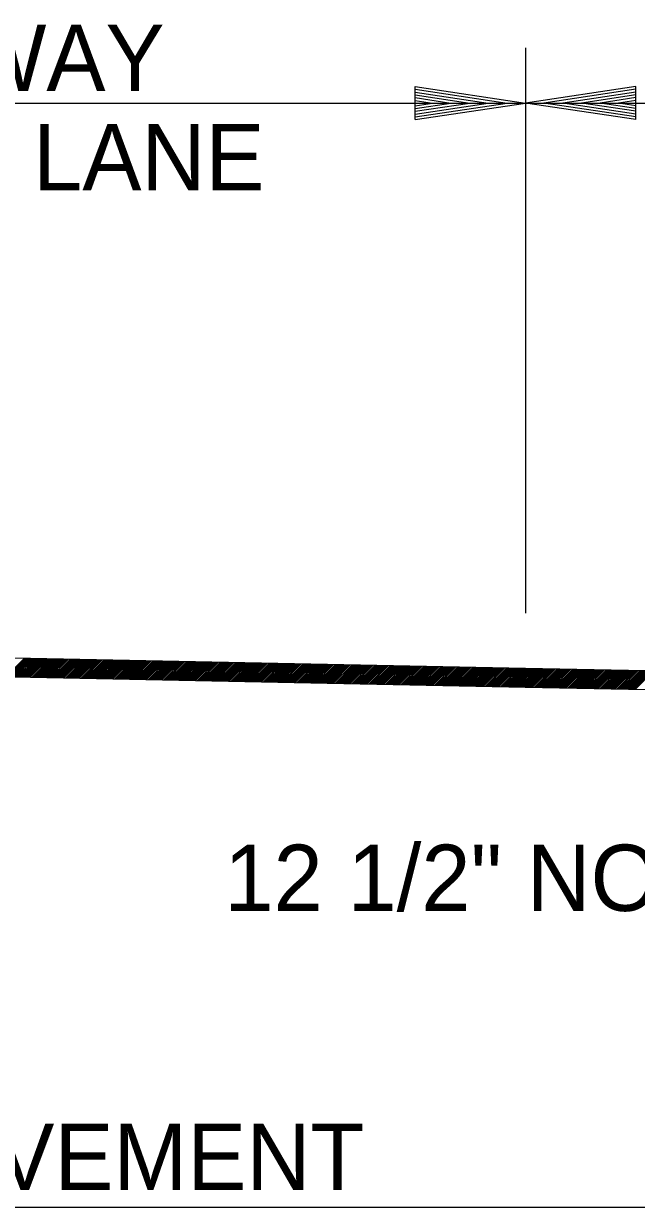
# Model space of a CAD drawing. Extents: x 2263886 to 2266026, y -3122850 to -3121850.
# Drawn here: x 2265601.06 to 2265606.6, y -3122413.5 to -3122402.78 of the extents above; entities that cross this region are included whole.
import ezdxf

# ---------------------------------------------------------------- set-up
doc = ezdxf.new("R2010")
doc.units = 0
doc.layers.add('R_Border Prem', color=7, linetype='Continuous')

msp = doc.modelspace()

# ---------------------------------------------------------------- linework, layer by layer
at = {"layer": 'R_Border Prem'}
for p, q in [((2265605.599, -3122403.003), (2265605.599, -3122407.503)), ((2265604.599, -3122403.353), (2265605.599, -3122403.503)), ((2265604.599, -3122403.653), (2265604.599, -3122403.353)), ((2265604.599, -3122403.378), (2265605.432, -3122403.503)), ((2265604.599, -3122403.404), (2265605.26, -3122403.503)), ((2265604.599, -3122403.429), (2265605.094, -3122403.503)), ((2265606.599, -3122403.353), (2265605.599, -3122403.503)), ((2265606.599, -3122403.378), (2265605.766, -3122403.503)), ((2265606.599, -3122403.404), (2265605.938, -3122403.503)), ((2265606.599, -3122403.429), (2265606.105, -3122403.503)), ((2265606.599, -3122403.653), (2265606.599, -3122403.353)), ((2265593.599, -3122403.503), (2265605.599, -3122403.503)), ((2265604.599, -3122403.454), (2265604.924, -3122403.503)), ((2265604.599, -3122403.48), (2265604.757, -3122403.503)), ((2265604.599, -3122403.653), (2265605.599, -3122403.503)), ((2265604.599, -3122403.552), (2265604.924, -3122403.503)), ((2265604.599, -3122403.603), (2265605.26, -3122403.503)), ((2265604.599, -3122403.628), (2265605.432, -3122403.503)), ((2265604.599, -3122403.578), (2265605.094, -3122403.503)), ((2265604.599, -3122403.527), (2265604.757, -3122403.503)), ((2265605.599, -3122403.503), (2265617.599, -3122403.503)), ((2265606.599, -3122403.653), (2265605.599, -3122403.503)), ((2265606.599, -3122403.628), (2265605.766, -3122403.503)), ((2265606.599, -3122403.603), (2265605.938, -3122403.503)), ((2265606.599, -3122403.578), (2265606.105, -3122403.503)), ((2265606.599, -3122403.454), (2265606.274, -3122403.503)), ((2265606.599, -3122403.552), (2265606.274, -3122403.503)), ((2265606.599, -3122403.48), (2265606.441, -3122403.503)), ((2265606.599, -3122403.527), (2265606.441, -3122403.503)), ((2265605.599, -3122407.503), (2265605.599, -3122408.123)), ((2265605.599, -3122408.623), (2265599.599, -3122408.503)), ((2265600.893, -3122408.699), (2265601.059, -3122408.532)), ((2265600.906, -3122408.699), (2265601.073, -3122408.533)), ((2265600.92, -3122408.7), (2265601.087, -3122408.533)), ((2265600.934, -3122408.7), (2265601.101, -3122408.533)), ((2265600.948, -3122408.7), (2265601.115, -3122408.533)), ((2265600.962, -3122408.7), (2265601.129, -3122408.534)), ((2265600.976, -3122408.701), (2265601.142, -3122408.534)), ((2265600.99, -3122408.701), (2265601.156, -3122408.534)), ((2265601.004, -3122408.701), (2265601.17, -3122408.534)), ((2265601.017, -3122408.701), (2265601.184, -3122408.535)), ((2265601.031, -3122408.702), (2265601.198, -3122408.535)), ((2265601.045, -3122408.702), (2265601.212, -3122408.535)), ((2265601.059, -3122408.702), (2265601.226, -3122408.536)), ((2265601.073, -3122408.703), (2265601.24, -3122408.536)), ((2265601.087, -3122408.703), (2265601.253, -3122408.536)), ((2265601.101, -3122408.703), (2265601.267, -3122408.536)), ((2265601.114, -3122408.703), (2265601.281, -3122408.537)), ((2265601.128, -3122408.704), (2265601.295, -3122408.537)), ((2265601.142, -3122408.704), (2265601.309, -3122408.537)), ((2265601.156, -3122408.704), (2265601.323, -3122408.538)), ((2265601.17, -3122408.705), (2265601.337, -3122408.538)), ((2265601.184, -3122408.705), (2265601.35, -3122408.538)), ((2265601.198, -3122408.705), (2265601.364, -3122408.538)), ((2265601.211, -3122408.705), (2265601.378, -3122408.539)), ((2265601.225, -3122408.706), (2265601.392, -3122408.539)), ((2265601.239, -3122408.706), (2265601.406, -3122408.539)), ((2265601.253, -3122408.706), (2265601.42, -3122408.539)), ((2265601.267, -3122408.706), (2265601.434, -3122408.54)), ((2265601.281, -3122408.707), (2265601.447, -3122408.54)), ((2265601.295, -3122408.707), (2265601.461, -3122408.54)), ((2265601.309, -3122408.707), (2265601.475, -3122408.541)), ((2265601.322, -3122408.708), (2265601.489, -3122408.541)), ((2265601.336, -3122408.708), (2265601.503, -3122408.541)), ((2265601.35, -3122408.708), (2265601.517, -3122408.541)), ((2265601.364, -3122408.708), (2265601.531, -3122408.542)), ((2265601.378, -3122408.709), (2265601.545, -3122408.542)), ((2265601.392, -3122408.709), (2265601.558, -3122408.542)), ((2265601.406, -3122408.709), (2265601.572, -3122408.543)), ((2265601.419, -3122408.709), (2265601.586, -3122408.543)), ((2265601.433, -3122408.71), (2265601.6, -3122408.543)), ((2265601.447, -3122408.71), (2265601.614, -3122408.543)), ((2265601.461, -3122408.71), (2265601.628, -3122408.544)), ((2265601.475, -3122408.711), (2265601.642, -3122408.544)), ((2265601.489, -3122408.711), (2265601.655, -3122408.544)), ((2265601.503, -3122408.711), (2265601.669, -3122408.544)), ((2265601.516, -3122408.711), (2265601.683, -3122408.545)), ((2265601.53, -3122408.712), (2265601.697, -3122408.545)), ((2265601.544, -3122408.712), (2265601.711, -3122408.545)), ((2265601.558, -3122408.712), (2265601.725, -3122408.546)), ((2265601.572, -3122408.713), (2265601.739, -3122408.546)), ((2265601.586, -3122408.713), (2265601.753, -3122408.546)), ((2265601.6, -3122408.713), (2265601.766, -3122408.546)), ((2265601.614, -3122408.713), (2265601.78, -3122408.547)), ((2265601.627, -3122408.714), (2265601.794, -3122408.547)), ((2265601.641, -3122408.714), (2265601.808, -3122408.547)), ((2265601.655, -3122408.714), (2265601.822, -3122408.548)), ((2265601.669, -3122408.714), (2265601.836, -3122408.548)), ((2265601.683, -3122408.715), (2265601.85, -3122408.548)), ((2265601.697, -3122408.715), (2265601.863, -3122408.548)), ((2265601.711, -3122408.715), (2265601.877, -3122408.549)), ((2265601.724, -3122408.716), (2265601.891, -3122408.549)), ((2265601.738, -3122408.716), (2265601.905, -3122408.549)), ((2265601.752, -3122408.716), (2265601.919, -3122408.549)), ((2265601.766, -3122408.716), (2265601.933, -3122408.55)), ((2265601.78, -3122408.717), (2265601.947, -3122408.55)), ((2265601.794, -3122408.717), (2265601.96, -3122408.55)), ((2265601.808, -3122408.717), (2265601.974, -3122408.551)), ((2265601.822, -3122408.718), (2265601.988, -3122408.551)), ((2265601.835, -3122408.718), (2265602.002, -3122408.551)), ((2265601.849, -3122408.718), (2265602.016, -3122408.551)), ((2265601.863, -3122408.718), (2265602.03, -3122408.552)), ((2265601.877, -3122408.719), (2265602.044, -3122408.552)), ((2265601.891, -3122408.719), (2265602.058, -3122408.552)), ((2265601.905, -3122408.719), (2265602.071, -3122408.553)), ((2265601.919, -3122408.719), (2265602.085, -3122408.553)), ((2265601.932, -3122408.72), (2265602.099, -3122408.553)), ((2265601.946, -3122408.72), (2265602.113, -3122408.553)), ((2265601.96, -3122408.72), (2265602.127, -3122408.554)), ((2265601.974, -3122408.721), (2265602.141, -3122408.554)), ((2265601.988, -3122408.721), (2265602.155, -3122408.554)), ((2265602.002, -3122408.721), (2265602.168, -3122408.554)), ((2265602.016, -3122408.721), (2265602.182, -3122408.555)), ((2265602.029, -3122408.722), (2265602.196, -3122408.555)), ((2265602.043, -3122408.722), (2265602.21, -3122408.555)), ((2265602.057, -3122408.722), (2265602.224, -3122408.556)), ((2265602.071, -3122408.723), (2265602.238, -3122408.556)), ((2265602.085, -3122408.723), (2265602.252, -3122408.556)), ((2265602.099, -3122408.723), (2265602.266, -3122408.556)), ((2265602.113, -3122408.723), (2265602.279, -3122408.557)), ((2265602.127, -3122408.724), (2265602.293, -3122408.557)), ((2265602.14, -3122408.724), (2265602.307, -3122408.557)), ((2265602.154, -3122408.724), (2265602.321, -3122408.557)), ((2265602.168, -3122408.724), (2265602.335, -3122408.558)), ((2265602.182, -3122408.725), (2265602.349, -3122408.558)), ((2265602.196, -3122408.725), (2265602.363, -3122408.558)), ((2265602.21, -3122408.725), (2265602.376, -3122408.559)), ((2265602.224, -3122408.726), (2265602.39, -3122408.559)), ((2265602.237, -3122408.726), (2265602.404, -3122408.559)), ((2265602.251, -3122408.726), (2265602.418, -3122408.559)), ((2265602.265, -3122408.726), (2265602.432, -3122408.56)), ((2265602.279, -3122408.727), (2265602.446, -3122408.56)), ((2265602.293, -3122408.727), (2265602.46, -3122408.56)), ((2265602.307, -3122408.727), (2265602.473, -3122408.561)), ((2265602.321, -3122408.728), (2265602.487, -3122408.561)), ((2265602.335, -3122408.728), (2265602.501, -3122408.561)), ((2265602.348, -3122408.728), (2265602.515, -3122408.561)), ((2265602.362, -3122408.728), (2265602.529, -3122408.562)), ((2265602.376, -3122408.729), (2265602.543, -3122408.562)), ((2265602.39, -3122408.729), (2265602.557, -3122408.562)), ((2265602.404, -3122408.729), (2265602.571, -3122408.562)), ((2265602.418, -3122408.729), (2265602.584, -3122408.563)), ((2265602.432, -3122408.73), (2265602.598, -3122408.563)), ((2265602.445, -3122408.73), (2265602.612, -3122408.563)), ((2265602.459, -3122408.73), (2265602.626, -3122408.564)), ((2265602.473, -3122408.731), (2265602.64, -3122408.564)), ((2265602.487, -3122408.731), (2265602.654, -3122408.564)), ((2265602.501, -3122408.731), (2265602.668, -3122408.564)), ((2265602.515, -3122408.731), (2265602.681, -3122408.565)), ((2265602.529, -3122408.732), (2265602.695, -3122408.565)), ((2265602.542, -3122408.732), (2265602.709, -3122408.565)), ((2265602.556, -3122408.732), (2265602.723, -3122408.566)), ((2265602.57, -3122408.733), (2265602.737, -3122408.566)), ((2265602.584, -3122408.733), (2265602.751, -3122408.566)), ((2265602.598, -3122408.733), (2265602.765, -3122408.566)), ((2265602.612, -3122408.733), (2265602.779, -3122408.567)), ((2265602.626, -3122408.734), (2265602.792, -3122408.567)), ((2265602.64, -3122408.734), (2265602.806, -3122408.567)), ((2265602.653, -3122408.734), (2265602.82, -3122408.567)), ((2265602.667, -3122408.734), (2265602.834, -3122408.568)), ((2265602.681, -3122408.735), (2265602.848, -3122408.568)), ((2265602.695, -3122408.735), (2265602.862, -3122408.568)), ((2265602.709, -3122408.735), (2265602.876, -3122408.569)), ((2265602.723, -3122408.736), (2265602.889, -3122408.569)), ((2265602.737, -3122408.736), (2265602.903, -3122408.569)), ((2265602.75, -3122408.736), (2265602.917, -3122408.569)), ((2265602.764, -3122408.736), (2265602.931, -3122408.57)), ((2265602.778, -3122408.737), (2265602.945, -3122408.57)), ((2265602.792, -3122408.737), (2265602.959, -3122408.57)), ((2265602.806, -3122408.737), (2265602.973, -3122408.571)), ((2265602.82, -3122408.738), (2265602.986, -3122408.571)), ((2265602.834, -3122408.738), (2265603, -3122408.571)), ((2265602.848, -3122408.738), (2265603.014, -3122408.571)), ((2265602.861, -3122408.738), (2265603.028, -3122408.572)), ((2265602.875, -3122408.739), (2265603.042, -3122408.572)), ((2265602.889, -3122408.739), (2265603.056, -3122408.572)), ((2265602.903, -3122408.739), (2265603.07, -3122408.572)), ((2265602.917, -3122408.739), (2265603.084, -3122408.573)), ((2265602.931, -3122408.74), (2265603.097, -3122408.573)), ((2265602.945, -3122408.74), (2265603.111, -3122408.573)), ((2265602.958, -3122408.74), (2265603.125, -3122408.574)), ((2265602.972, -3122408.741), (2265603.139, -3122408.574)), ((2265602.986, -3122408.741), (2265603.153, -3122408.574)), ((2265603, -3122408.741), (2265603.167, -3122408.574)), ((2265603.014, -3122408.741), (2265603.181, -3122408.575)), ((2265603.028, -3122408.742), (2265603.194, -3122408.575)), ((2265603.042, -3122408.742), (2265603.208, -3122408.575)), ((2265603.055, -3122408.742), (2265603.222, -3122408.576)), ((2265603.069, -3122408.742), (2265603.236, -3122408.576)), ((2265603.083, -3122408.743), (2265603.25, -3122408.576)), ((2265603.097, -3122408.743), (2265603.264, -3122408.576)), ((2265603.111, -3122408.743), (2265603.278, -3122408.577)), ((2265603.125, -3122408.744), (2265603.292, -3122408.577)), ((2265603.139, -3122408.744), (2265603.305, -3122408.577)), ((2265603.153, -3122408.744), (2265603.319, -3122408.577)), ((2265603.166, -3122408.744), (2265603.333, -3122408.578)), ((2265603.18, -3122408.745), (2265603.347, -3122408.578)), ((2265603.194, -3122408.745), (2265603.361, -3122408.578)), ((2265603.208, -3122408.745), (2265603.375, -3122408.579)), ((2265603.222, -3122408.746), (2265603.389, -3122408.579)), ((2265603.236, -3122408.746), (2265603.402, -3122408.579)), ((2265603.25, -3122408.746), (2265603.416, -3122408.579)), ((2265603.263, -3122408.746), (2265603.43, -3122408.58)), ((2265603.277, -3122408.747), (2265603.444, -3122408.58)), ((2265603.291, -3122408.747), (2265603.458, -3122408.58)), ((2265603.305, -3122408.747), (2265603.472, -3122408.581)), ((2265603.319, -3122408.747), (2265603.486, -3122408.581)), ((2265603.333, -3122408.748), (2265603.499, -3122408.581)), ((2265603.347, -3122408.748), (2265603.513, -3122408.581)), ((2265603.361, -3122408.748), (2265603.527, -3122408.582)), ((2265603.374, -3122408.749), (2265603.541, -3122408.582)), ((2265603.388, -3122408.749), (2265603.555, -3122408.582)), ((2265603.402, -3122408.749), (2265603.569, -3122408.582)), ((2265603.416, -3122408.749), (2265603.583, -3122408.583)), ((2265603.43, -3122408.75), (2265603.597, -3122408.583)), ((2265599.599, -3122408.673), (2265605.596, -3122408.793)), ((2265603.444, -3122408.75), (2265603.61, -3122408.583)), ((2265603.458, -3122408.75), (2265603.624, -3122408.584)), ((2265603.471, -3122408.751), (2265603.638, -3122408.584)), ((2265603.485, -3122408.751), (2265603.652, -3122408.584)), ((2265603.499, -3122408.751), (2265603.666, -3122408.584)), ((2265603.513, -3122408.751), (2265603.68, -3122408.585)), ((2265603.527, -3122408.752), (2265603.694, -3122408.585)), ((2265603.541, -3122408.752), (2265603.707, -3122408.585)), ((2265603.555, -3122408.752), (2265603.721, -3122408.585)), ((2265603.568, -3122408.752), (2265603.735, -3122408.586)), ((2265603.582, -3122408.753), (2265603.749, -3122408.586)), ((2265603.596, -3122408.753), (2265603.763, -3122408.586)), ((2265603.61, -3122408.753), (2265603.777, -3122408.587)), ((2265603.624, -3122408.754), (2265603.791, -3122408.587)), ((2265603.638, -3122408.754), (2265603.805, -3122408.587)), ((2265603.652, -3122408.754), (2265603.818, -3122408.587)), ((2265603.666, -3122408.754), (2265603.832, -3122408.588)), ((2265603.679, -3122408.755), (2265603.846, -3122408.588)), ((2265603.693, -3122408.755), (2265603.86, -3122408.588)), ((2265603.707, -3122408.755), (2265603.874, -3122408.589)), ((2265603.721, -3122408.756), (2265603.888, -3122408.589)), ((2265603.735, -3122408.756), (2265603.902, -3122408.589)), ((2265603.749, -3122408.756), (2265603.915, -3122408.589)), ((2265603.763, -3122408.756), (2265603.929, -3122408.59)), ((2265603.776, -3122408.757), (2265603.943, -3122408.59)), ((2265603.79, -3122408.757), (2265603.957, -3122408.59)), ((2265603.804, -3122408.757), (2265603.971, -3122408.59)), ((2265603.818, -3122408.757), (2265603.985, -3122408.591)), ((2265603.832, -3122408.758), (2265603.999, -3122408.591)), ((2265603.846, -3122408.758), (2265604.012, -3122408.591)), ((2265603.86, -3122408.758), (2265604.026, -3122408.592)), ((2265603.874, -3122408.759), (2265604.04, -3122408.592)), ((2265603.887, -3122408.759), (2265604.054, -3122408.592)), ((2265603.901, -3122408.759), (2265604.068, -3122408.592)), ((2265603.915, -3122408.759), (2265604.082, -3122408.593)), ((2265603.929, -3122408.76), (2265604.096, -3122408.593)), ((2265603.943, -3122408.76), (2265604.11, -3122408.593)), ((2265603.957, -3122408.76), (2265604.123, -3122408.594)), ((2265603.971, -3122408.761), (2265604.137, -3122408.594)), ((2265603.984, -3122408.761), (2265604.151, -3122408.594)), ((2265603.998, -3122408.761), (2265604.165, -3122408.594)), ((2265604.012, -3122408.761), (2265604.179, -3122408.595)), ((2265604.026, -3122408.762), (2265604.193, -3122408.595)), ((2265604.04, -3122408.762), (2265604.207, -3122408.595)), ((2265604.054, -3122408.762), (2265604.22, -3122408.595)), ((2265604.068, -3122408.762), (2265604.234, -3122408.596)), ((2265604.081, -3122408.763), (2265604.248, -3122408.596)), ((2265604.095, -3122408.763), (2265604.262, -3122408.596)), ((2265604.109, -3122408.763), (2265604.276, -3122408.597)), ((2265604.123, -3122408.764), (2265604.29, -3122408.597)), ((2265604.137, -3122408.764), (2265604.304, -3122408.597)), ((2265604.151, -3122408.764), (2265604.318, -3122408.597)), ((2265604.165, -3122408.764), (2265604.331, -3122408.598)), ((2265604.179, -3122408.765), (2265604.345, -3122408.598)), ((2265604.192, -3122408.765), (2265604.359, -3122408.598)), ((2265604.206, -3122408.765), (2265604.373, -3122408.599)), ((2265604.22, -3122408.766), (2265604.387, -3122408.599)), ((2265604.234, -3122408.766), (2265604.401, -3122408.599)), ((2265604.248, -3122408.766), (2265604.415, -3122408.599)), ((2265604.262, -3122408.766), (2265604.428, -3122408.6)), ((2265604.276, -3122408.767), (2265604.442, -3122408.6)), ((2265604.289, -3122408.767), (2265604.456, -3122408.6)), ((2265604.303, -3122408.767), (2265604.47, -3122408.6)), ((2265604.317, -3122408.767), (2265604.484, -3122408.601)), ((2265604.331, -3122408.768), (2265604.498, -3122408.601)), ((2265604.345, -3122408.768), (2265604.512, -3122408.601)), ((2265604.359, -3122408.768), (2265604.525, -3122408.602)), ((2265604.373, -3122408.769), (2265604.539, -3122408.602)), ((2265604.387, -3122408.769), (2265604.553, -3122408.602)), ((2265604.4, -3122408.769), (2265604.567, -3122408.602)), ((2265604.414, -3122408.769), (2265604.581, -3122408.603)), ((2265604.428, -3122408.77), (2265604.595, -3122408.603)), ((2265604.442, -3122408.77), (2265604.609, -3122408.603)), ((2265604.456, -3122408.77), (2265604.623, -3122408.604)), ((2265604.47, -3122408.771), (2265604.636, -3122408.604)), ((2265604.484, -3122408.771), (2265604.65, -3122408.604)), ((2265604.497, -3122408.771), (2265604.664, -3122408.604)), ((2265604.511, -3122408.771), (2265604.678, -3122408.605)), ((2265604.525, -3122408.772), (2265604.692, -3122408.605)), ((2265604.539, -3122408.772), (2265604.706, -3122408.605)), ((2265604.553, -3122408.772), (2265604.72, -3122408.605)), ((2265604.567, -3122408.772), (2265604.733, -3122408.606)), ((2265604.581, -3122408.773), (2265604.747, -3122408.606)), ((2265604.594, -3122408.773), (2265604.761, -3122408.606)), ((2265604.608, -3122408.773), (2265604.775, -3122408.607)), ((2265604.622, -3122408.774), (2265604.789, -3122408.607)), ((2265604.636, -3122408.774), (2265604.803, -3122408.607)), ((2265604.65, -3122408.774), (2265604.817, -3122408.607)), ((2265604.664, -3122408.774), (2265604.831, -3122408.608)), ((2265604.678, -3122408.775), (2265604.844, -3122408.608)), ((2265604.692, -3122408.775), (2265604.858, -3122408.608)), ((2265604.705, -3122408.775), (2265604.872, -3122408.609)), ((2265604.719, -3122408.775), (2265604.886, -3122408.609)), ((2265604.733, -3122408.776), (2265604.9, -3122408.609)), ((2265604.747, -3122408.776), (2265604.914, -3122408.609)), ((2265604.761, -3122408.776), (2265604.928, -3122408.61)), ((2265604.775, -3122408.777), (2265604.941, -3122408.61)), ((2265604.789, -3122408.777), (2265604.955, -3122408.61)), ((2265604.802, -3122408.777), (2265604.969, -3122408.61)), ((2265604.816, -3122408.777), (2265604.983, -3122408.611)), ((2265604.83, -3122408.778), (2265604.997, -3122408.611)), ((2265604.844, -3122408.778), (2265605.011, -3122408.611)), ((2265604.858, -3122408.778), (2265605.025, -3122408.612)), ((2265604.872, -3122408.779), (2265605.038, -3122408.612)), ((2265604.886, -3122408.779), (2265605.052, -3122408.612)), ((2265604.9, -3122408.779), (2265605.066, -3122408.612)), ((2265604.913, -3122408.779), (2265605.08, -3122408.613)), ((2265604.927, -3122408.78), (2265605.094, -3122408.613)), ((2265604.941, -3122408.78), (2265605.108, -3122408.613)), ((2265604.955, -3122408.78), (2265605.122, -3122408.614)), ((2265604.969, -3122408.78), (2265605.136, -3122408.614)), ((2265604.983, -3122408.781), (2265605.149, -3122408.614)), ((2265604.997, -3122408.781), (2265605.163, -3122408.614)), ((2265605.01, -3122408.781), (2265605.177, -3122408.615)), ((2265605.024, -3122408.782), (2265605.191, -3122408.615)), ((2265605.038, -3122408.782), (2265605.205, -3122408.615)), ((2265605.052, -3122408.782), (2265605.219, -3122408.615)), ((2265605.066, -3122408.782), (2265605.233, -3122408.616)), ((2265605.08, -3122408.783), (2265605.246, -3122408.616)), ((2265605.094, -3122408.783), (2265605.26, -3122408.616)), ((2265605.107, -3122408.783), (2265605.274, -3122408.617)), ((2265605.121, -3122408.784), (2265605.288, -3122408.617)), ((2265605.135, -3122408.784), (2265605.302, -3122408.617)), ((2265605.149, -3122408.784), (2265605.316, -3122408.617)), ((2265605.163, -3122408.784), (2265605.33, -3122408.618)), ((2265605.177, -3122408.785), (2265605.344, -3122408.618)), ((2265605.191, -3122408.785), (2265605.357, -3122408.618)), ((2265605.205, -3122408.785), (2265605.371, -3122408.618)), ((2265605.218, -3122408.785), (2265605.385, -3122408.619)), ((2265605.232, -3122408.786), (2265605.399, -3122408.619)), ((2265605.246, -3122408.786), (2265605.413, -3122408.619)), ((2265605.26, -3122408.786), (2265605.427, -3122408.62)), ((2265605.274, -3122408.787), (2265605.441, -3122408.62)), ((2265605.288, -3122408.787), (2265605.454, -3122408.62)), ((2265605.302, -3122408.787), (2265605.468, -3122408.62)), ((2265605.315, -3122408.787), (2265605.482, -3122408.621)), ((2265605.329, -3122408.788), (2265605.496, -3122408.621)), ((2265605.343, -3122408.788), (2265605.51, -3122408.621)), ((2265605.357, -3122408.788), (2265605.524, -3122408.622)), ((2265605.371, -3122408.789), (2265605.538, -3122408.622)), ((2265605.385, -3122408.789), (2265605.551, -3122408.622)), ((2265605.399, -3122408.789), (2265605.565, -3122408.622)), ((2265605.413, -3122408.789), (2265605.579, -3122408.623)), ((2265605.426, -3122408.79), (2265605.593, -3122408.623)), ((2265605.44, -3122408.79), (2265605.607, -3122408.623)), ((2265605.454, -3122408.79), (2265605.621, -3122408.623)), ((2265605.468, -3122408.79), (2265605.635, -3122408.624)), ((2265605.482, -3122408.791), (2265605.649, -3122408.624)), ((2265605.496, -3122408.791), (2265605.662, -3122408.624)), ((2265605.51, -3122408.791), (2265605.676, -3122408.625)), ((2265605.523, -3122408.792), (2265605.69, -3122408.625)), ((2265605.537, -3122408.792), (2265605.704, -3122408.625)), ((2265605.551, -3122408.792), (2265605.718, -3122408.625)), ((2265605.565, -3122408.792), (2265605.732, -3122408.626)), ((2265605.579, -3122408.793), (2265605.746, -3122408.626)), ((2265605.593, -3122408.793), (2265605.759, -3122408.626)), ((2265610.599, -3122408.723), (2265605.599, -3122408.623)), ((2265605.607, -3122408.793), (2265605.773, -3122408.627)), ((2265605.62, -3122408.794), (2265605.787, -3122408.627)), ((2265605.634, -3122408.794), (2265605.801, -3122408.627)), ((2265605.648, -3122408.794), (2265605.815, -3122408.627)), ((2265605.662, -3122408.794), (2265605.829, -3122408.628)), ((2265605.676, -3122408.795), (2265605.843, -3122408.628)), ((2265605.69, -3122408.795), (2265605.857, -3122408.628)), ((2265605.704, -3122408.795), (2265605.87, -3122408.628)), ((2265605.718, -3122408.795), (2265605.884, -3122408.629)), ((2265605.731, -3122408.796), (2265605.898, -3122408.629)), ((2265605.745, -3122408.796), (2265605.912, -3122408.629)), ((2265605.759, -3122408.796), (2265605.926, -3122408.63)), ((2265605.773, -3122408.797), (2265605.94, -3122408.63)), ((2265605.787, -3122408.797), (2265605.954, -3122408.63)), ((2265605.801, -3122408.797), (2265605.967, -3122408.63)), ((2265605.815, -3122408.797), (2265605.981, -3122408.631)), ((2265605.828, -3122408.798), (2265605.995, -3122408.631)), ((2265605.842, -3122408.798), (2265606.009, -3122408.631)), ((2265605.856, -3122408.798), (2265606.023, -3122408.632)), ((2265605.87, -3122408.799), (2265606.037, -3122408.632)), ((2265605.884, -3122408.799), (2265606.051, -3122408.632)), ((2265605.898, -3122408.799), (2265606.064, -3122408.632)), ((2265605.912, -3122408.799), (2265606.078, -3122408.633)), ((2265605.926, -3122408.8), (2265606.092, -3122408.633)), ((2265605.939, -3122408.8), (2265606.106, -3122408.633)), ((2265605.953, -3122408.8), (2265606.12, -3122408.633)), ((2265605.967, -3122408.8), (2265606.134, -3122408.634)), ((2265605.981, -3122408.801), (2265606.148, -3122408.634)), ((2265605.995, -3122408.801), (2265606.162, -3122408.634)), ((2265606.009, -3122408.801), (2265606.175, -3122408.635)), ((2265606.023, -3122408.802), (2265606.189, -3122408.635)), ((2265606.036, -3122408.802), (2265606.203, -3122408.635)), ((2265606.05, -3122408.802), (2265606.217, -3122408.635)), ((2265606.064, -3122408.802), (2265606.231, -3122408.636)), ((2265606.078, -3122408.803), (2265606.245, -3122408.636)), ((2265606.092, -3122408.803), (2265606.259, -3122408.636)), ((2265606.106, -3122408.803), (2265606.272, -3122408.637)), ((2265606.12, -3122408.803), (2265606.286, -3122408.637)), ((2265606.133, -3122408.804), (2265606.3, -3122408.637)), ((2265606.147, -3122408.804), (2265606.314, -3122408.637)), ((2265606.161, -3122408.804), (2265606.328, -3122408.638)), ((2265606.175, -3122408.805), (2265606.342, -3122408.638)), ((2265606.189, -3122408.805), (2265606.356, -3122408.638)), ((2265606.203, -3122408.805), (2265606.37, -3122408.638)), ((2265606.217, -3122408.805), (2265606.383, -3122408.639)), ((2265606.231, -3122408.806), (2265606.397, -3122408.639)), ((2265606.244, -3122408.806), (2265606.411, -3122408.639)), ((2265606.258, -3122408.806), (2265606.425, -3122408.64)), ((2265606.272, -3122408.807), (2265606.439, -3122408.64)), ((2265606.286, -3122408.807), (2265606.453, -3122408.64)), ((2265606.3, -3122408.807), (2265606.467, -3122408.64)), ((2265606.314, -3122408.807), (2265606.48, -3122408.641)), ((2265606.328, -3122408.808), (2265606.494, -3122408.641)), ((2265606.341, -3122408.808), (2265606.508, -3122408.641)), ((2265606.355, -3122408.808), (2265606.522, -3122408.642)), ((2265606.369, -3122408.808), (2265606.536, -3122408.642)), ((2265606.383, -3122408.809), (2265606.55, -3122408.642)), ((2265606.397, -3122408.809), (2265606.564, -3122408.642)), ((2265606.411, -3122408.809), (2265606.577, -3122408.643)), ((2265606.425, -3122408.81), (2265606.591, -3122408.643)), ((2265606.439, -3122408.81), (2265606.605, -3122408.643)), ((2265606.452, -3122408.81), (2265606.619, -3122408.643)), ((2265606.466, -3122408.81), (2265606.633, -3122408.644)), ((2265606.48, -3122408.811), (2265606.647, -3122408.644)), ((2265606.494, -3122408.811), (2265606.661, -3122408.644)), ((2265606.508, -3122408.811), (2265606.675, -3122408.645)), ((2265606.522, -3122408.812), (2265606.688, -3122408.645)), ((2265606.536, -3122408.812), (2265606.702, -3122408.645)), ((2265606.549, -3122408.812), (2265606.716, -3122408.645)), ((2265606.563, -3122408.812), (2265606.73, -3122408.646)), ((2265606.577, -3122408.813), (2265606.744, -3122408.646)), ((2265606.591, -3122408.813), (2265606.758, -3122408.646)), ((2265605.596, -3122408.793), (2265610.596, -3122408.893)), ((2265588.602, -3122413.503), (2265610.596, -3122413.503))]:
    msp.add_line(p, q, dxfattribs=at)

# ---------------------------------------------------------------- texts
for s, p in [('12\'-0" TWO-WAY', (2265596.098, -3122403.393)), ('LEFT TURNING LANE', (2265595.078, -3122404.293)), ('12 1/2" NOTCH', (2265602.871, -3122410.819))]:
    msp.add_text(s, height=0.6, dxfattribs=at).set_placement(p)
msp.add_text('22\'-0" EXISTING PAVEMENT', height=0.6, rotation=360, dxfattribs=at).set_placement((2265593.493, -3122413.346))

doc.saveas('drawing.dxf')
